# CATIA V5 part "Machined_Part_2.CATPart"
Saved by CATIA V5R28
Part number: Mach_Part_2
Bounding box of the stored display mesh (mm): x -177.8 to 177.8, y 0 to 101.6, z -396.421 to 390.077
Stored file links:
  C:\Users\rsz0866\Documents\007_CATIA_STEP-Files_and_Test_Models\0001_Machined_Parts_Models\Machined_Part_2.CATPart
  C:\Users\phf1501\Documents\Philshome\Models\Functional Molded Parts\Functional modeling part two.CATProduct
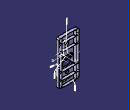
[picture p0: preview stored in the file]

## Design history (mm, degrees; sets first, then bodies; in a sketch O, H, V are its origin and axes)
AxisSystem1: origin (0, 0, 0), X (1, 0, 0), Y (0, 1, 0), Z (0, 0, 1)
SpdDefaultsManager1
f4a2d38f3ddc11d3a929006094b99c4b_11 "CATTPSSet"
Set1 "Part Profiles"
  Sketch1 "Profile" on Plane1, origin (0, 50.8, 0), H (-1, 0, 0), V (0, 0, 1)
    line L1 (-177.8, 431.8) -> (177.8, 431.8)
    line L2 (177.8, 431.8) -> (177.8, -431.8)
    line L3 (177.8, -431.8) -> (-177.8, -431.8)
    line L4 (-177.8, -431.8) -> (-177.8, 431.8)
    distance V L2 = 177.8
    distance H L1 = 431.8
    length L2 = 863.6
    length L1 = 355.6
    horizontal: L1 H, L3 H
    vertical: L2 V, L4 V
  Sketch2 "Ribs" on Plane1, origin (0, 50.8, 0), H (-1, 0, 0), V (0, 0, 1)
    line L1 (-127, 457.2) -> (-127, -457.2)
    line L2 (127, 457.2) -> (127, -457.2)
    line L3 (-228.6, 279.4) -> (228.6, 279.4)
    line L4 (-228.6, 152.4) -> (228.6, 152.4)
    line L5 (-228.6, -152.4) -> (228.6, -152.4)
    line L6 (-228.6, -279.4) -> (228.6, -279.4)
    vertical: L1 V
    horizontal: L3 H
  Sketch3 "Internal features" on Plane1, origin (0, 50.8, 0), H (-1, 0, 0), V (0, 0, 1)
    circle A1 centre (0, 215.9) radius 25.4
    point P1 (0, 215.9)
    point P2 (0, 190.5)
    circle A2 centre (0, -215.9) radius 25.4
    point P3 (0, -215.9)
    arc A3 centre (76.2, 0) radius 25.4 from (76.2, -25.4) to (76.2, 25.4) ccw
    point P4 (76.2, 0)
    arc A4 centre (-76.2, 0) radius 25.4 from (-76.2, 25.4) to (-76.2, -25.4) ccw
    point P5 (-76.2, 0)
    line L1 (-76.2, 25.4) -> (76.2, 25.4)
    line L2 (76.2, -25.4) -> (-76.2, -25.4)
    coincidence: P1 V, A1 P2, P2 V, P3 V, P4 H, P5 H
    tangency: L1 A3, L2 A3, L2 A4, L1 A4
  Sketch4 "Boss profile" on Plane1, origin (0, 50.8, 0), H (-1, 0, 0), V (0, 0, 1)
    circle A1 centre (-101.6, -127) radius 19.05
    circle A2 centre (101.6, -127) radius 19.05
  Sketch5 "Cutout" on face of MainFunctionalSetSolid1, origin (0, 57.15, 0), H (-1, 0, 0), V (0, 0, 1)
    line L1 (-56.6874, -49.6703) -> (47.6742, -49.6703)
    line L2 (66.7242, -68.7203) -> (66.7242, -104.6674)
    line L3 (47.6742, -123.7174) -> (-56.6874, -123.7174)
    line L4 (-75.7374, -104.6674) -> (-75.7374, -68.7203)
    arc A1 centre (47.6742, -68.7203) radius 19.05 from (47.6742, -49.6703) to (66.7242, -68.7203) cw
    arc A2 centre (-56.6874, -68.7203) radius 19.05 from (-56.6874, -49.6703) to (-75.7374, -68.7203) ccw
    arc A3 centre (-56.6874, -104.6674) radius 19.05 from (-75.7374, -104.6674) to (-56.6874, -123.7174) ccw
    arc A4 centre (47.6742, -104.6674) radius 19.05 from (47.6742, -123.7174) to (66.7242, -104.6674) ccw
    radius A1 = 19.05
    radius A2 = 19.05
    radius A3 = 19.05
    radius A4 = 19.05
    horizontal: L1 H, L3 H
    vertical: L2 V, L4 V
    tangency: A1 L1, A1 L2, A2 L1, A2 L4, A3 L4, A3 L3, A4 L3, A4 L2
  Sketch6 "Pocket" on face of MainFunctionalSetSolid1, origin (0, 57.15, 0), H (-1, 0, 0), V (0, 0, 1)
    line L1 (-68.391, -296.2435) -> (86.424, -312.0714)
    arc A1 centre (85.1323, -324.7055) radius 12.7 from (86.424, -312.0714) to (86.6944, -337.3091) cw
    line L2 (86.6944, -337.3091) -> (-68.1206, -356.4968)
    line L3 (-82.3827, -343.8932) -> (-82.3827, -308.8776)
    arc A2 centre (-69.6827, -308.8776) radius 12.7 from (-68.391, -296.2435) to (-82.3827, -308.8776) ccw
    arc A3 centre (-69.6827, -343.8932) radius 12.7 from (-82.3827, -343.8932) to (-68.1206, -356.4968) ccw
    radius A2 = 12.7
    radius A3 = 12.7
    radius A1 = 12.7
    tangency: A1 L1, A1 L2, A2 L1, A2 L3, A3 L3, A3 L2
    vertical: L3 V
  Sketch7 "All Pocket" on face of MainFunctionalSetSolid1, origin (0, 101.6, 0), H (-1, 0, 0), V (0, 0, 1)
    ellipse A1 centre (111.125, -369.6196) semi-axes 12.7282, 12.7 rotation 90 from (112.1626, -382.3053) to (123.825, -369.6196)
    frozenspline C1
    ellipse A2 centre (-111.125, -369.6196) semi-axes 12.7282, 12.7 rotation 270 from (-123.825, -369.6196) to (-112.1626, -382.3053)
    line L1 (-123.825, -288.925) -> (-123.825, -369.6196)
    arc A3 centre (-117.475, -288.925) radius 6.35 from (-117.475, -282.575) to (-123.825, -288.925) ccw
    line L2 (-117.475, -282.575) -> (117.475, -282.575)
    arc A4 centre (117.475, -288.925) radius 6.35 from (123.825, -288.925) to (117.475, -282.575) ccw
    line L3 (123.825, -288.925) -> (123.825, -369.6196)
    arc A5 centre (-158.75, -295.275) radius 12.7 from (-158.75, -282.575) to (-171.45, -295.275) ccw
    line L4 (-136.525, -282.575) -> (-158.75, -282.575)
    arc A6 centre (-136.525, -288.925) radius 6.35 from (-130.175, -288.925) to (-136.525, -282.575) ccw
    line L5 (-130.175, -288.925) -> (-130.175, -366.6387)
    ellipse A7 centre (-142.875, -366.6387) semi-axes 12.7282, 12.7 rotation 90 from (-144.2061, -379.2968) to (-130.175, -366.6387)
    arc A8 centre (1.8993, 1003.9352) radius 1390.9269 from (-160.227, -377.5106) to (-144.2061, -379.2968) ccw
    ellipse A9 centre (-158.75, -364.8688) semi-axes 12.7282, 12.7 rotation 90 from (-171.45, -364.8688) to (-160.227, -377.5106)
    line L6 (-171.45, -364.8688) -> (-171.45, -295.275)
    arc A10 centre (-158.75, -168.275) radius 12.7 from (-158.75, -155.575) to (-171.45, -168.275) ccw
    line L7 (-136.525, -155.575) -> (-158.75, -155.575)
    arc A11 centre (-136.525, -161.925) radius 6.35 from (-130.175, -161.925) to (-136.525, -155.575) ccw
    line L8 (-130.175, -161.925) -> (-130.175, -269.875)
    arc A12 centre (-136.525, -269.875) radius 6.35 from (-136.525, -276.225) to (-130.175, -269.875) ccw
    line L9 (-136.525, -276.225) -> (-158.75, -276.225)
    arc A13 centre (-158.75, -263.525) radius 12.7 from (-171.45, -263.525) to (-158.75, -276.225) ccw
    line L10 (-171.45, -263.525) -> (-171.45, -168.275)
    arc A14 centre (158.75, -295.275) radius 12.7 from (171.45, -295.275) to (158.75, -282.575) ccw
    line L11 (171.45, -364.8688) -> (171.45, -295.275)
    ellipse A15 centre (158.75, -364.8688) semi-axes 12.7282, 12.7 rotation 90 from (160.227, -377.5106) to (171.45, -364.8688)
    arc A16 centre (-1.8993, 1003.9351) radius 1390.9268 from (144.2061, -379.2968) to (160.227, -377.5106) ccw
    ellipse A17 centre (142.875, -366.6387) semi-axes 12.7282, 12.7 rotation 270 from (130.175, -366.6387) to (144.2061, -379.2968)
    line L12 (130.175, -288.925) -> (130.175, -366.6387)
    arc A18 centre (136.525, -288.925) radius 6.35 from (136.525, -282.575) to (130.175, -288.925) ccw
    line L13 (136.525, -282.575) -> (158.75, -282.575)
    arc A19 centre (158.75, -168.275) radius 12.7 from (171.45, -168.275) to (158.75, -155.575) ccw
    line L14 (171.45, -263.525) -> (171.45, -168.275)
    arc A20 centre (158.75, -263.525) radius 12.7 from (158.75, -276.225) to (171.45, -263.525) ccw
    line L15 (136.525, -276.225) -> (158.75, -276.225)
    arc A21 centre (136.525, -269.875) radius 6.35 from (130.175, -269.875) to (136.525, -276.225) ccw
    line L16 (130.175, -161.925) -> (130.175, -269.875)
    arc A22 centre (136.525, -161.925) radius 6.35 from (136.525, -155.575) to (130.175, -161.925) ccw
    line L17 (136.525, -155.575) -> (158.75, -155.575)
    arc A23 centre (-158.75, -136.525) radius 12.7 from (-171.45, -136.525) to (-158.75, -149.225) ccw
    line L18 (-171.45, -136.525) -> (-171.45, 136.525)
    arc A24 centre (-158.75, 136.525) radius 12.7 from (-158.75, 149.225) to (-171.45, 136.525) ccw
    line L19 (-136.525, 149.225) -> (-158.75, 149.225)
    arc A25 centre (-136.525, 142.875) radius 6.35 from (-130.175, 142.875) to (-136.525, 149.225) ccw
    line L20 (-130.175, 142.875) -> (-130.175, -142.875)
    arc A26 centre (-136.525, -142.875) radius 6.35 from (-136.525, -149.225) to (-130.175, -142.875) ccw
    line L21 (-136.525, -149.225) -> (-158.75, -149.225)
    arc A27 centre (158.75, -136.525) radius 12.7 from (158.75, -149.225) to (171.45, -136.525) ccw
    line L22 (136.525, -149.225) -> (158.75, -149.225)
    arc A28 centre (136.525, -142.875) radius 6.35 from (130.175, -142.875) to (136.525, -149.225) ccw
    line L23 (130.175, 142.875) -> (130.175, -142.875)
    arc A29 centre (136.525, 142.875) radius 6.35 from (136.525, 149.225) to (130.175, 142.875) ccw
    line L24 (136.525, 149.225) -> (158.75, 149.225)
    arc A30 centre (158.75, 136.525) radius 12.7 from (171.45, 136.525) to (158.75, 149.225) ccw
    line L25 (171.45, -136.525) -> (171.45, 136.525)
    arc A31 centre (158.75, 168.275) radius 12.7 from (158.75, 155.575) to (171.45, 168.275) ccw
    line L26 (136.525, 155.575) -> (158.75, 155.575)
    arc A32 centre (136.525, 161.925) radius 6.35 from (130.175, 161.925) to (136.525, 155.575) ccw
    line L27 (130.175, 269.875) -> (130.175, 161.925)
    arc A33 centre (136.525, 269.875) radius 6.35 from (136.525, 276.225) to (130.175, 269.875) ccw
    line L28 (136.525, 276.225) -> (158.75, 276.225)
    arc A34 centre (158.75, 263.525) radius 12.7 from (171.45, 263.525) to (158.75, 276.225) ccw
    line L29 (171.45, 168.275) -> (171.45, 263.525)
    arc A35 centre (-158.75, 168.275) radius 12.7 from (-171.45, 168.275) to (-158.75, 155.575) ccw
    line L30 (-171.45, 168.275) -> (-171.45, 263.525)
    arc A36 centre (-158.75, 263.525) radius 12.7 from (-158.75, 276.225) to (-171.45, 263.525) ccw
    line L31 (-136.525, 276.225) -> (-158.75, 276.225)
    arc A37 centre (-136.525, 269.875) radius 6.35 from (-130.175, 269.875) to (-136.525, 276.225) ccw
    line L32 (-130.175, 269.875) -> (-130.175, 161.925)
    arc A38 centre (-136.525, 161.925) radius 6.35 from (-136.525, 155.575) to (-130.175, 161.925) ccw
    line L33 (-136.525, 155.575) -> (-158.75, 155.575)
    arc A39 centre (-158.75, 295.275) radius 12.7 from (-171.45, 295.275) to (-158.75, 282.575) ccw
    line L34 (-171.45, 295.275) -> (-171.45, 361.6527)
    ellipse A40 centre (-158.75, 361.6527) semi-axes 12.7282, 12.7 rotation 270 from (-159.7339, 374.3427) to (-171.45, 361.6527)
    arc A41 centre (0.8326, -1687.4015) radius 2067.9871 from (-143.761, 375.5244) to (-159.7339, 374.3427) ccw
    ellipse A42 centre (-142.875, 362.8272) semi-axes 12.7282, 12.7 rotation 90 from (-130.175, 362.8272) to (-143.761, 375.5244)
    line L35 (-130.175, 288.925) -> (-130.175, 362.8272)
    arc A43 centre (-136.525, 288.925) radius 6.35 from (-136.525, 282.575) to (-130.175, 288.925) ccw
    line L36 (-136.525, 282.575) -> (-158.75, 282.575)
    ellipse A44 centre (-111.125, 364.8054) semi-axes 12.7282, 12.7 rotation 270 from (-111.8148, 377.5148) to (-123.825, 364.8054)
    arc A45 centre (0, -1672.2492) radius 2052.8115 from (111.8148, 377.5148) to (-111.8148, 377.5148) ccw
    ellipse A46 centre (111.125, 364.8054) semi-axes 12.7282, 12.7 rotation 90 from (123.825, 364.8054) to (111.8148, 377.5148)
    line L37 (123.825, 288.925) -> (123.825, 364.8054)
    arc A47 centre (117.475, 288.925) radius 6.35 from (117.475, 282.575) to (123.825, 288.925) ccw
    line L38 (-117.475, 282.575) -> (117.475, 282.575)
    arc A48 centre (-117.475, 288.925) radius 6.35 from (-123.825, 288.925) to (-117.475, 282.575) ccw
    line L39 (-123.825, 288.925) -> (-123.825, 364.8054)
    ellipse A49 centre (142.875, 362.8272) semi-axes 12.7282, 12.7 rotation 270 from (143.761, 375.5244) to (130.175, 362.8272)
    arc A50 centre (-0.8326, -1687.4015) radius 2067.9871 from (159.7339, 374.3427) to (143.761, 375.5244) ccw
    ellipse A51 centre (158.75, 361.6527) semi-axes 12.7282, 12.7 rotation 90 from (171.45, 361.6527) to (159.7339, 374.3427)
    line L40 (171.45, 295.275) -> (171.45, 361.6527)
    arc A52 centre (158.75, 295.275) radius 12.7 from (158.75, 282.575) to (171.45, 295.275) ccw
    line L41 (136.525, 282.575) -> (158.75, 282.575)
    arc A53 centre (136.525, 288.925) radius 6.35 from (130.175, 288.925) to (136.525, 282.575) ccw
    line L42 (130.175, 288.925) -> (130.175, 362.8272)
    line L43 (-117.475, 149.225) -> (117.475, 149.225)
    arc A54 centre (117.475, 142.875) radius 6.35 from (123.825, 142.875) to (117.475, 149.225) ccw
    line L44 (123.825, 142.875) -> (123.825, -142.875)
    arc A55 centre (117.475, -142.875) radius 6.35 from (117.475, -149.225) to (123.825, -142.875) ccw
    line L45 (-117.475, -149.225) -> (117.475, -149.225)
    arc A56 centre (-117.475, -142.875) radius 6.35 from (-123.825, -142.875) to (-117.475, -149.225) ccw
    line L46 (-123.825, 142.875) -> (-123.825, -142.875)
    arc A57 centre (-117.475, 142.875) radius 6.35 from (-117.475, 149.225) to (-123.825, 142.875) ccw
    line L47 (-117.475, 276.225) -> (117.475, 276.225)
    arc A58 centre (117.475, 269.875) radius 6.35 from (123.825, 269.875) to (117.475, 276.225) ccw
    line L48 (123.825, 269.875) -> (123.825, 161.925)
    arc A59 centre (117.475, 161.925) radius 6.35 from (117.475, 155.575) to (123.825, 161.925) ccw
    line L49 (-117.475, 155.575) -> (117.475, 155.575)
    arc A60 centre (-117.475, 161.925) radius 6.35 from (-123.825, 161.925) to (-117.475, 155.575) ccw
    line L50 (-123.825, 269.875) -> (-123.825, 161.925)
    arc A61 centre (-117.475, 269.875) radius 6.35 from (-117.475, 276.225) to (-123.825, 269.875) ccw
    line L51 (-117.475, -155.575) -> (117.475, -155.575)
    arc A62 centre (117.475, -161.925) radius 6.35 from (123.825, -161.925) to (117.475, -155.575) ccw
    line L52 (123.825, -161.925) -> (123.825, -269.875)
    arc A63 centre (117.475, -269.875) radius 6.35 from (117.475, -276.225) to (123.825, -269.875) ccw
    line L53 (-117.475, -276.225) -> (117.475, -276.225)
    arc A64 centre (-117.475, -269.875) radius 6.35 from (-123.825, -269.875) to (-117.475, -276.225) ccw
    line L54 (-123.825, -161.925) -> (-123.825, -269.875)
    arc A65 centre (-117.475, -161.925) radius 6.35 from (-117.475, -155.575) to (-123.825, -161.925) ccw
Set2
  Plane1: stored without definition
  DatumSurface1
  DatumSurface2
Body1 (main body)
  MainFunctionalSetSolid1
  Chamfer1: length 1.27, angle 45, on edge [face of MainFunctionalSetSolid1 | face of MainFunctionalSetSolid1] (x12)
  Fillet1: radius 12.7, on edge [face of MainFunctionalSetSolid1 | face of MainFunctionalSetSolid1] (x28)
  Fillet2: radius 19.05, on edge [face of MainFunctionalSetSolid1 | face of MainFunctionalSetSolid1] (x4)
  Fillet3: radius 3.175, on face of MainFunctionalSetSolid1 (x15); edge [face of MainFunctionalSetSolid1 | face of MainFunctionalSetSolid1] (x2)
